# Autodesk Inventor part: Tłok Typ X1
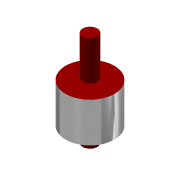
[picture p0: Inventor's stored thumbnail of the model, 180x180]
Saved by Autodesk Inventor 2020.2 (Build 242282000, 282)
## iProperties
Created: 2005-10
Part Number: Tłok Typ X1
Document SubType Name: Modeling
Designer: F.Stasiak
Stock Number: Tłok Typ X1
Density: 1 g/cm^3
Mass: 211.179 g
Surface Area: 231.287 cm^2
Volume: 211.179 cm^3
Material: Ogólny
Appearance: Czerwony (matowy)
Manager: www.cadconsulting.pl
Company: Fabian Stasiak CAD Consulting
Author: F.Stasiak
Subject: Zbiór ćwiczeń. Autodesk Inventor 2020. Kurs podstawowy
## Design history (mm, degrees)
sketch "Szkic1"
  geometry: C1 r 10 at (0, 0); 1 further point
  constraints: 1 centre point, 1 coincident
  dimensions: "d0" = 20 diameter of C1
extrude "Wyciągnięcie proste1" new body sketch "Szkic1" distance "d1" = 100; taper "d2" = 0 deg
node "Płaszczyzna konstrukcyjna1"
sketch "Szkic2"
  geometry: C1 r 10 at (0, 0) reference; C2 r 33.25 at (2.7, -2.7)
  constraints: 1 centre point
  dimensions: "d11" = 2.7 horizontal distance of C2.centre C1.centre; "d12" = 2.7 horizontal distance of C1.centre C2.centre (= d11); "d13" = 66.5 diameter of C2
extrude "Wyciągnięcie proste2" join sketch "Szkic2" stored distance "d7" = 54; taper "d8" = 0 deg
sketch "Szkic3"
  geometry: C1 r 3.998 at (-17.329, -17.779)
  constraints: 1 centre point
extrude "Wyciągnięcie proste3" cut sketch "Szkic3" distance "d9" = 5; taper "d10" = 0 deg
sketch "Szkic4"
  geometry: C1 r 10 at (0, 0) reference
extrude "Wyciągnięcie proste4" join sketch "Szkic4" distance "d14" = 30; taper "d15" = 0 deg
node "Bryła1"
node "Korpusy bryłowe"
node "Korpusy powierzchniowe"
